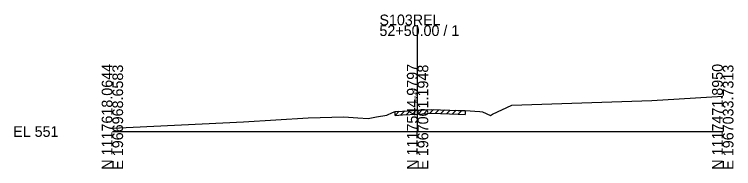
# Model space of a CAD drawing. Extents: x -26 to 163, y -10 to 24518.
# Drawn here: x -25.7 to 162.8, y 2990.3 to 3030.6 of the extents above; entities that cross this region are included whole.
import ezdxf

# ---------------------------------------------------------------- set-up
doc = ezdxf.new("R2010")
doc.units = 0
for name, color, linetype in [('RD_GPK_XS_Cell', 7, 'Continuous'), ('RD_XS_ExGround', 7, 'Continuous'), ('RD_XS_ExPaveRet', 7, 'Continuous'), ('RD_XS_TX_Elev_EX', 7, 'Continuous')]:
    doc.layers.add(name, color=color, linetype=linetype)

msp = doc.modelspace()

# ---------------------------------------------------------------- linework, layer by layer
at = {"layer": 'RD_GPK_XS_Cell'}
for p, q in [((80, 3000), (80, 3027.79)), ((0, 3000), (80, 3000)), ((80, 3000), (160, 3000))]:
    msp.add_line(p, q, dxfattribs=at)
at = {"layer": 'RD_XS_ExGround'}
msp.add_lwpolyline([(0, 3000.88), (34.35, 3002.54), (51.3, 3003.55), (60.7, 3003.83), (64.3, 3003.59), (67.05, 3003.43), (69.22, 3003.8), (71.9, 3004.26), (73.43, 3004.97), (74.11, 3005.23), (76.02, 3005.35), (80, 3005.57), (83.7, 3005.77), (90.67, 3005.54), (92.51, 3005.48), (96.28, 3005.21), (96.99, 3005.17), (99.07, 3004.2), (99.63, 3004.52), (104.73, 3006.92), (141.44, 3008.1), (160, 3009.26)], dxfattribs=at)
at = {"layer": 'RD_XS_ExPaveRet'}
for p, q in [((74.11, 3004.23), (75.18, 3005.3)), ((74.11, 3004.23), (74.11, 3005.23)), ((75.61, 3004.33), (76.67, 3005.39)), ((77.11, 3004.41), (78.17, 3005.47)), ((78.61, 3004.49), (79.67, 3005.55)), ((80.11, 3004.58), (81.17, 3005.64)), ((81.61, 3004.66), (82.67, 3005.72)), ((83.11, 3004.74), (84.13, 3005.76)), ((84.61, 3004.74), (85.58, 3005.71)), ((86.11, 3004.69), (87.08, 3005.66)), ((87.61, 3004.64), (88.58, 3005.61)), ((89.11, 3004.59), (90.08, 3005.56)), ((90.61, 3004.54), (91.59, 3005.51)), ((92.51, 3005.48), (92.51, 3004.48)), ((74.11, 3004.23), (76.02, 3004.35)), ((76.02, 3004.35), (80, 3004.57)), ((80, 3004.57), (83.7, 3004.77)), ((83.7, 3004.77), (90.67, 3004.54)), ((90.67, 3004.54), (92.51, 3004.48))]:
    msp.add_line(p, q, dxfattribs=at)

# ---------------------------------------------------------------- texts
at = {"layer": 'RD_GPK_XS_Cell'}
for s, p in [('S103REL', (70, 3027.79)), ('52+50.00 / 1', (70, 3024.99)), ('EL 551', (-26, 2998.6))]:
    msp.add_text(s, height=2.8, dxfattribs=at).set_placement(p)
for s, p in [('N 1117618.0644', (0, 2990)), ('E 1966968.6583', (2.8, 2990)), ('N 1117544.9797', (80, 2990)), ('E 1967001.1948', (82.8, 2990)), ('N 1117471.8950', (160, 2990)), ('E 1967033.7313', (162.8, 2990))]:
    msp.add_text(s, height=2.8, rotation=90, dxfattribs=at).set_placement(p)
at = {"layer": 'RD_XS_TX_Elev_EX'}
msp.add_text('556.57', height=0.8, rotation=90, dxfattribs=at).set_placement((79.9, 3007.57))

doc.saveas('drawing.dxf')
